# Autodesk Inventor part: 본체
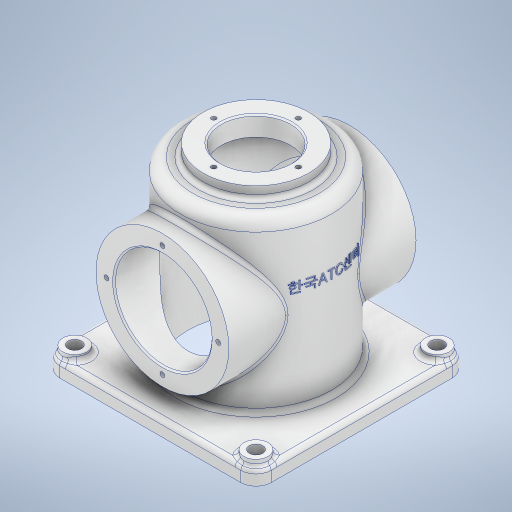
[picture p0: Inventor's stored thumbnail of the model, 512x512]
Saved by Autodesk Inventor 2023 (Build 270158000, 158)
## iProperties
Created: 2025-05
Part Number: 본체
Material: 알루미늄 6061
Document SubType Name: Modeling
Designer: Admin
Density: 2.7 g/cm^3
Appearance: 알루미늄 - 평지
Mass: 1392.48 g
Surface Area: 1192.64 cm^2
Volume: 515.735 cm^3
Author: Admin
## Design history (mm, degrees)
sketch "스케치1"
  geometry: L1 (-70, 70)-(70, 70); L2 (70, 70)-(70, -70); L3 (70, -70)-(-70, -70); L4 (-70, -70)-(-70, 70); L5 (-70, 70)-(70, -70); L6 (70, 70)-(-70, -70); 1 further point
  constraints: 12 end point, 2 midpoint, 2 parallel, 1 horizontal, 1 perpendicular
  dimensions: "d0" = 140 distance of L1.end L2.end; "d1" = 140 distance of L2.end L3.end
extrude "돌출1" new body sketch "스케치1" distance "d2" = 10; taper "d3" = 0 deg
sketch "스케치2"
  geometry: C1 r 50 at (0, 0); 1 further point
  constraints: 1 centre point, 1 coincident
  dimensions: "d4" = 100 diameter of C1
extrude "돌출2" join sketch "스케치2" distance "d5" = 112; taper "d6" = 0 deg
sketch "스케치3"
  geometry: C1 r 35 at (0, 0); 1 further point
  constraints: 1 centre point, 1 coincident
  dimensions: "d7" = 70 diameter of C1
extrude "돌출3" join sketch "스케치3" distance "d8" = 8; taper "d9" = 0 deg
sketch "스케치4"
  geometry: L1 (60, -60)-(-60, -60); L2 (-60, -60)-(-60, 60); L3 (-60, 60)-(60, 60); L4 (60, 60)-(60, -60); L5 (60, -60)-(-60, 60); L6 (-60, -60)-(60, 60); C1 r 8 at (-60, -60); C2 r 8 at (-60, 60); C3 r 8 at (60, -60); C4 r 8 at (60, 60); 1 further point
  constraints: 12 end point, 4 centre point, 4 coincident, 2 midpoint, 2 parallel, 1 horizontal, 1 perpendicular
  dimensions: "d10" = 120 distance of L1.end L2.end; "d11" = 120 distance of L2.end L3.end; "d12" = 16 diameter of C1; "d13" = 16 diameter of C2; "d14" = 16 diameter of C4; "d15" = 16 diameter of C3
extrude "돌출4" join sketch "스케치4" distance "d16" = 4; taper "d17" = 0 deg
sketch "스케치5"
  geometry: L1 (70, 0)-(-70, 0) reference; L2 (0, -26)-(0, 156) reference; C1 r 44 at (0, 65); 1 further point
  constraints: 1 centre point, 1 midpoint
  dimensions: "d18" = 88 diameter of C1; "d19" = 65 distance from line of L1 C1.centre
extrude "돌출5" join sketch "스케치5" stored distance "d20" = 124; taper "d21" = 0 deg
sketch "스케치8" dims "d23" = 74
  geometry: L1 (0, -91)-(0, 91) reference; L2 (-98, -65)-(98, -65) reference; 7 further points
  constraints: 1 coincident, 1 midpoint, 1 point on line, 1 vertical alignment, 7 other
  dimensions: "d24" = 65 distance from line of L2 point (0, 0); "d27" = 360 deg dimension on point (0, 0) point (0, 37) (derived)
hole "구멍1" sketch "스케치8" at (0, 37), (-37, 0), (0, -37), (37, 0) diameter "d29" = 3.242; stored, may be unused: countersink angle "d33" = 90 deg, drill point angle "d35" = 118 deg; dims "d30" = 8, "d31" = 4, "d32" = 2, "d34" = 10
sketch "스케치10"
  geometry: L1 (-98, -65)-(98, -65) reference; L2 (0, -91)-(0, 91) reference; C1 r 32 at (0, 0); 1 further point
  constraints: 1 centre point, 1 midpoint
  dimensions: "d36" = 64 diameter of C1; "d37" = 65 distance from line of L1 C1.centre
extrude "돌출6" cut sketch "스케치10" distance "d38" = 124; taper "d39" = 0 deg
sketch "스케치11" dims "d40" = 56
  geometry: L1 (-98, 0)-(98, 0) reference; 6 further points
  constraints: 1 coincident, 1 horizontal alignment, 1 point on line, 7 other
  dimensions: "d43" = 360 deg dimension on point (0, 0) point (-28, 0) (derived)
hole "구멍2" sketch "스케치11" at (-28, 0), (0, -28), (28, 0), (0, 28) diameter "d45" = 3.242; stored, may be unused: countersink angle "d49" = 90 deg, drill point angle "d51" = 118 deg; dims "d46" = 8, "d47" = 4, "d48" = 2, "d50" = 10
sketch "스케치12"
  geometry: C1 r 23 at (0, 0); 1 further point
  constraints: 1 centre point, 1 coincident
  dimensions: "d52" = 46 diameter of C1
extrude "돌출7" cut sketch "스케치12" distance "d53" = 13; taper "d54" = 0 deg
sketch "스케치13"
  geometry: L1 (-158, -60)-(38, -60) reference; L2 (-60, 38)-(-60, -158) reference; C1 r 4.5 at (0, 0); C2 r 8 at (0, 0) reference; C3 r 4.5 at (-120, 0); C4 r 4.5 at (-120, -120); C5 r 4.5 at (0, -120); 1 further point
  constraints: 4 centre point, 3 symmetric about line, 1 concentric, 3 other
  dimensions: "d55" = 9 diameter of C1
extrude "돌출8" cut sketch "스케치13" extent not by distance; stored distance "d56" = 0; taper "d57" = 0 deg
sketch "스케치14"
  geometry: C1 r 45 at (0, 0); 1 further point
  constraints: 1 centre point, 1 coincident
  dimensions: "d58" = 90 diameter of C1
extrude "돌출9" cut sketch "스케치14" distance "d59" = 117; taper "d60" = 0 deg
node "작업 평면1"
sketch "스케치15"
  geometry: L1 (0, 70)-(0, -70) reference; L2 (-130.999, 0)-(173.5, 0) reference; 2 further points
  constraints: 1 point on line, 1 other
  dimensions: "d65" = 80 distance from line of L1 point (80, 0)
feature "엠보싱2" sketch "스케치15" dims "d0" = 140, "d1" = 140, "d10" = 120, "d11" = 120, "d12" = 16, "d13" = 16, "d14" = 16, "d15" = 16, "d66" = 0.5, "d67" = 0
fillet "모깎기1" dims "d68" = 10
fillet "모깎기2" dims "d69" = 3
fillet "모깎기3" dims "d70" = 3
fillet "모깎기4" dims "d71" = 8
chamfer "모따기1" distance "d72" = 1; stored, may be unused: second distance "d73" = 2, angle "d74" = 45 deg
fillet "모깎기5" dims "d75" = 3
fillet "모깎기6" dims "d76" = 3
node "솔리드1"
mirror "미러1"
feature "A9D066F2-1C7D-4E18-AEED-F7BC21143FA4" dims "d29" = 3.242, "d30" = 8, "d31" = 4, "d32" = 2, "d33" = 90 deg, "d34" = 10, "d35" = 118 deg
other parameters: "d61" = 89
